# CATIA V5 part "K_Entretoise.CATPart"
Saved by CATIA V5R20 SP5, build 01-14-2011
Part number: Entretoise
Bounding box of the stored display mesh (mm): x -10.497 to 10.497, y -10.497 to 10.497, z -17.5 to 17.5
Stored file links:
  G:\Khaled_CFAO_2011\ST2M\ST2M_GR1\lpierredon\Khaled\CAD_thinkMOTION\K_Entretoise.CATPart
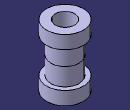
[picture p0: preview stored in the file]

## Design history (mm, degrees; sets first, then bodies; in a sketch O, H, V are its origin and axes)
Body1 (main body)
  Sketch1 on yz-plane, origin (0, 0, 0), H (0, 1, 0), V (0, 0, 1)
    line L1 (5.5, 0) -> (5.5, -17.5)
    point P1 (5.5, 0)
    point P2 (5.5, -17.5)
    line L2 (5.5, -17.5) -> (10.5, -17.5)
    point P3 (10.5, -17.5)
    line L3 (10.5, -17.5) -> (10.5, -10)
    point P4 (10.5, -10)
    line L4 (10.5, -10) -> (8, -10)
    point P5 (8, -10)
    line L5 (8, -10) -> (8, 0)
    point P6 (8, 0)
    reference intersected line E1 through (0, 0) direction (-1, 0) from xy-plane
    point P9 (0, 0)
    construction line L6 through (0, 0) direction (1, 0)
    construction line L7 through (0, 0) direction (0, -1)
    point P10 (5.5, 0)
    point P11 (5.5, 17.5)
    point P12 (10.5, 17.5)
    point P13 (10.5, 10)
    point P14 (8, 10)
    point P15 (8, 0)
    line L8 (5.5, 0) -> (5.5, 17.5)
    line L9 (5.5, 17.5) -> (10.5, 17.5)
    line L10 (10.5, 17.5) -> (10.5, 10)
    line L11 (10.5, 10) -> (8, 10)
    line L12 (8, 10) -> (8, 0)
    distance L1 V = 5.5
    distance L1 L5 = 2.5
    length L4 = 2.5
    length L3 = 7.5
    distance L2 L6 = 17.5
    coincidence: P1 H, P6 H, P1 P10, P6 P15
    vertical: L1 V, L3 V, L5 V
    horizontal: L2 H, L4 H
    symmetry: O P9 E1, H L6 E1, V L7 E1, P1 P10 E1, P2 P11 E1, P3 P12 E1, P4 P13 E1, P5 P14 E1, P6 P15 E1, L1 L8 E1, L2 L9 E1, L3 L10 E1, L4 L11 E1, L5 L12 E1
  Shaft1: profile Sketch1, axis Sketch1.V, angle 360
